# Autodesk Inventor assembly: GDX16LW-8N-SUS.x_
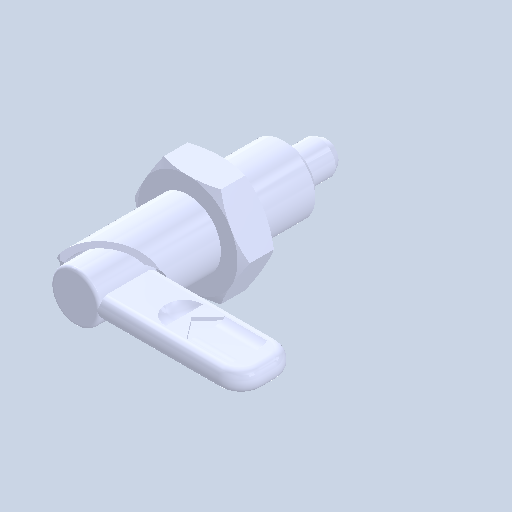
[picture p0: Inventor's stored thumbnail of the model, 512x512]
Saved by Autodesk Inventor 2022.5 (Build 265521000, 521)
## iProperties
Created: 2024-06
Part Number: GDX16LW-8N-SUS.x_
Document SubType Name: Assembly
Designer: ImaoCorp
Author: ImaoCorp
Sending System: SOLIDWORKS 2022-2022290
MC: AMD64
MC_MODEL: Intel64 Family 6 Model 60 Stepping 3, GenuineIntel
OS: Windows_NT
FRU: Parasolid Version 33.1, build 260,  4-25-2022
FORMAT: text
GUISE: transmit
KEY: FILEGDX16LW-8N-SUS.x_t
DATE: Wed Jun 12 09:32:41 2024
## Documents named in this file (4)
- Y:\5.更新分\2024年対応\xxxx_GDX\データ_imao品番\gdx16lw-8n-sus\GDX16LW-8N-SUS.x_.iam
- Y:\5.更新分\2024年対応\xxxx_GDX\データ_imao品番\gdx16lw-8n-sus\GDX16LW-8N-SUS_01.ipt
- Y:\5.更新分\2024年対応\xxxx_GDX\データ_imao品番\gdx16lw-8n-sus\GDX16LW-8N-SUS_02.ipt
- Y:\5.更新分\2024年対応\xxxx_GDX\データ_imao品番\gdx16lw-8n-sus\GDX16LW-8N-SUS_03.ipt
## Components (3 placed, 3 different names)
1. GDX16LW-8N-SUS_01
2. GDX16LW-8N-SUS_02
3. GDX16LW-8N-SUS_03
